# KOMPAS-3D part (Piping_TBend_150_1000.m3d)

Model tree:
1. Plane XY
2. Plane ZX
3. Plane ZY
4. X Axis
5. Y Axis
6. Z Axis
7. Origin
8. Sketch:1
9. Extrude:2  (labels: На расстояние 1; На расстояние 2)
     Толщина стенки 1 = 1; Толщина стенки 2 = 1
10. Sketch:3
11. Extrude:3  (labels: На расстояние 1; На расстояние 2)
     Толщина стенки 1 = 1; Толщина стенки 2 = 1; Расстояние 2 = 14
12. Sketch:4
13. Cut-Extrude:1  (labels: На расстояние 1; На расстояние 2)
     Толщина стенки 1 = 1; Толщина стенки 2 = 1; Расстояние 1 = 143; Расстояние 2 = 143
14. Sketch:6
15. Cut-Extrude:3  (labels: На расстояние 1; На расстояние 2)
     Толщина стенки 1 = 1; Толщина стенки 2 = 1; Расстояние 1 = 143; Расстояние 2 = 5.0494
16. Control point:1
17. Sketch:7
18. Attachment Point:1
19. Sketch:8
20. Attachment Point:2
21. Sketch:9
22. Attachment Point:3

Expressions: D-2*T; D1-2*T1
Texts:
  T-bend Dn 150
  Steel ASTM A295
  Three Point Plane
  Plane at Angle
  Line and Point Plane
  Axis through Two Vertices
  Axis of Feature
  Axis of Conical Surface
  Axis through Edge
  Приклеить элемент выдавливания
  Приклеить элемент вращения
  Приклеить кинематический элемент
  Приклеить элемент по сечениям
  Trim by Surface
  Trim by Sketch
  Feature with No History
  Intersection Axis of Two Planes
  Two Line Plane
  Line and Face Plane
  Bend by line
  Hole in sheet body
  Cut in sheet body
  Point in CM
  Linear Dimension from Line to Point
  Surface Finish Symbol
  Geometric Tolerance Symbol
  Текст на чертеже
  Линия-выноска #1
  Линия-выноска #2
  Линия-выноска #3
  Отклонения формы и база
  Марка координационной оси
  Марка/позиционное обозначение с линией-выноской
  Марка/позиционное обозначение на линии
  Марка/позиционное обозначение без линии-выноски
  Марки/позиционные обозначения с линией-выноской
  Марки/позиционные обозначения на линии
  Марки/позиционные обозначения без линии-выноски
  На расстояние 1
  На расстояние 2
